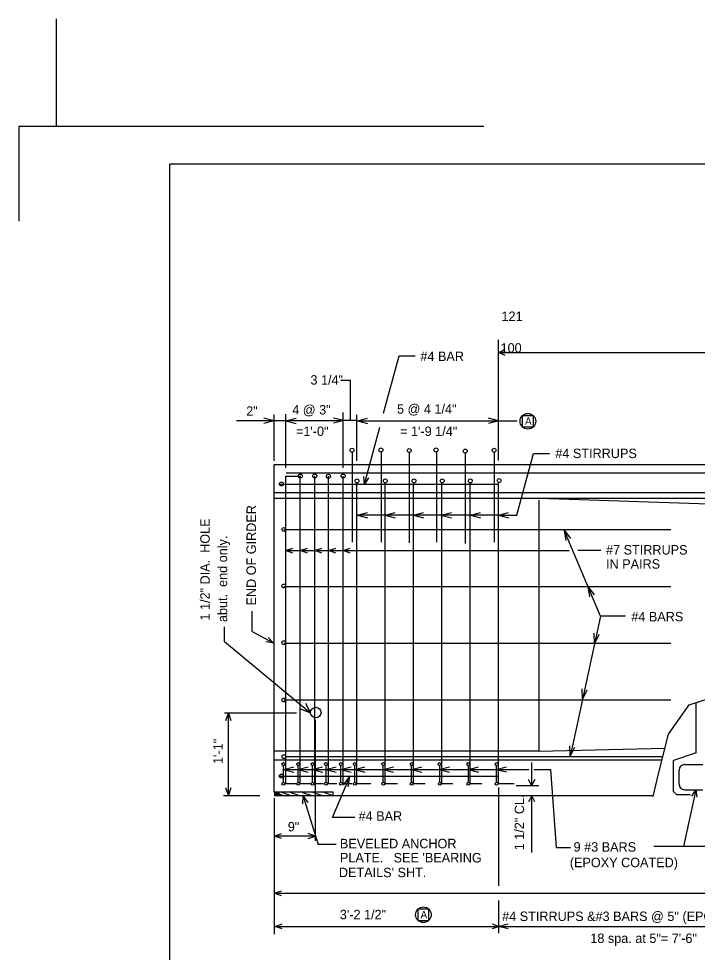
# Model space of a CAD drawing. Extents: x 1005 to 1133, y 2006 to 2074.
# Drawn here: x 1008.43 to 1032.36, y 2040.77 to 2073.7 of the extents above; entities that cross this region are included whole.
import ezdxf

# ---------------------------------------------------------------- set-up
doc = ezdxf.new("R2010")
doc.units = 0
for name, color, linetype in [('Level 1', 7, 'Continuous'), ('Level 2', 7, 'Continuous'), ('Level 5', 7, 'Continuous'), ('Level 6', 7, 'Continuous'), ('Level 60', 7, 'Continuous')]:
    doc.layers.add(name, color=color, linetype=linetype)

msp = doc.modelspace()

# ---------------------------------------------------------------- linework, layer by layer
at = {"layer": 'Level 1'}
for p, q in [((1024.831, 2069.894), (1008.43, 2069.894)), ((1008.43, 2069.894), (1008.43, 2066.554)), ((1013.763, 2012.562), (1013.763, 2068.561)), ((1097.431, 2068.561), (1013.763, 2068.561))]:
    msp.add_line(p, q, dxfattribs=at)
at = {"layer": 'Level 2'}
for p, q in [((1009.763, 2069.894), (1009.763, 2073.698)), ((1025.357, 2058.113), (1025.357, 2062.376)), ((1021.298, 2059.783), (1021.846, 2061.808)), ((1021.846, 2061.808), (1022.41, 2061.808)), ((1025.357, 2061.923), (1054.324, 2061.923)), ((1020.13, 2060.939), (1019.792, 2060.939)), ((1020.13, 2059.522), (1020.13, 2060.939)), ((1019.87, 2057.862), (1019.87, 2059.809)), ((1017.857, 2059.514), (1016.107, 2059.514)), ((1017.441, 2059.514), (1016.171, 2059.514)), ((1017.441, 2059.514), (1017.081, 2059.604)), ((1017.441, 2059.514), (1017.081, 2059.424)), ((1017.441, 2058.106), (1017.441, 2059.732)), ((1017.857, 2057.854), (1017.857, 2059.744)), ((1017.857, 2059.514), (1018.217, 2059.604)), ((1019.87, 2059.514), (1017.857, 2059.514)), ((1017.857, 2059.514), (1018.217, 2059.424)), ((1019.898, 2059.522), (1019.538, 2059.612)), ((1019.898, 2059.522), (1019.538, 2059.432)), ((1020.36, 2059.522), (1019.87, 2059.522)), ((1020.36, 2058.103), (1020.36, 2059.725)), ((1020.36, 2059.514), (1026.005, 2059.514)), ((1020.375, 2059.514), (1020.735, 2059.604)), ((1020.375, 2059.514), (1020.735, 2059.424)), ((1025.357, 2059.514), (1024.997, 2059.604)), ((1025.357, 2059.514), (1024.997, 2059.424)), ((1020.621, 2057.286), (1021.163, 2059.286)), ((1026.195, 2059.303), (1026.195, 2059.303)), ((1020.194, 2058.425), (1020.194, 2055.229)), ((1021.21, 2058.425), (1021.21, 2055.229)), ((1022.207, 2058.404), (1022.207, 2055.208)), ((1023.161, 2058.425), (1023.161, 2055.229)), ((1024.178, 2058.383), (1024.178, 2055.187)), ((1025.195, 2058.425), (1025.195, 2055.229)), ((1025.994, 2056.185), (1026.584, 2058.362)), ((1026.584, 2058.362), (1027.147, 2058.362)), ((1017.441, 2046.413), (1017.441, 2057.969)), ((1017.441, 2057.969), (1038.737, 2057.969)), ((1017.857, 2057.562), (1018.382, 2057.562)), ((1017.857, 2047.379), (1017.857, 2057.562)), ((1017.863, 2057.676), (1031.429, 2057.676)), ((1018.362, 2046.728), (1018.362, 2057.562)), ((1018.87, 2046.728), (1018.87, 2057.562)), ((1019.357, 2046.728), (1019.357, 2057.562)), ((1019.87, 2046.728), (1019.87, 2057.562)), ((1031.429, 2057.676), (1038.745, 2057.676)), ((1017.64, 2057.286), (1025.357, 2057.286)), ((1020.357, 2046.728), (1020.357, 2057.335)), ((1021.357, 2046.728), (1021.357, 2057.335)), ((1022.357, 2046.728), (1022.357, 2057.325)), ((1023.357, 2046.728), (1023.357, 2057.335)), ((1024.357, 2046.728), (1024.357, 2057.325)), ((1025.357, 2046.728), (1025.357, 2057.335)), ((1038.745, 2056.969), (1017.439, 2056.969)), ((1038.737, 2056.772), (1017.426, 2056.772)), ((1038.441, 2056.386), (1026.782, 2056.772)), ((1026.782, 2047.859), (1026.782, 2056.719)), ((1020.374, 2056.185), (1020.734, 2056.275)), ((1022.351, 2056.185), (1020.374, 2056.185)), ((1020.374, 2056.185), (1020.734, 2056.095)), ((1021.349, 2056.185), (1021.709, 2056.275)), ((1021.349, 2056.185), (1021.709, 2056.095)), ((1022.351, 2056.185), (1022.711, 2056.275)), ((1023.284, 2056.185), (1022.351, 2056.185)), ((1022.351, 2056.185), (1022.711, 2056.095)), ((1023.333, 2056.185), (1023.284, 2056.185)), ((1023.333, 2056.185), (1023.693, 2056.275)), ((1024.362, 2056.185), (1023.333, 2056.185)), ((1023.333, 2056.185), (1023.693, 2056.095)), ((1024.362, 2056.185), (1024.722, 2056.275)), ((1025.347, 2056.185), (1024.362, 2056.185)), ((1024.362, 2056.185), (1024.722, 2056.095)), ((1025.347, 2056.185), (1025.707, 2056.275)), ((1025.347, 2056.185), (1025.994, 2056.185)), ((1025.347, 2056.185), (1025.707, 2056.095)), ((1017.78, 2055.676), (1031.429, 2055.676)), ((1028.945, 2052.627), (1027.669, 2055.663)), ((1027.669, 2055.663), (1027.892, 2055.366)), ((1027.669, 2055.663), (1027.726, 2055.296)), ((1017.842, 2054.936), (1027.842, 2054.936)), ((1028.958, 2054.936), (1028.149, 2054.936)), ((1017.78, 2053.676), (1031.429, 2053.676)), ((1028.504, 2053.676), (1028.726, 2053.379)), ((1028.504, 2053.676), (1028.561, 2053.31)), ((1016.66, 2052.086), (1016.66, 2052.795)), ((1028.945, 2052.627), (1028.735, 2051.653)), ((1029.834, 2052.627), (1028.945, 2052.627)), ((1016.66, 2052.086), (1017.41, 2051.679)), ((1028.735, 2051.653), (1028.723, 2052.024)), ((1028.735, 2051.653), (1028.899, 2051.986)), ((1017.78, 2051.676), (1031.429, 2051.676)), ((1028.735, 2051.653), (1028.311, 2049.688)), ((1028.311, 2049.688), (1028.299, 2050.059)), ((1028.311, 2049.688), (1028.475, 2050.021)), ((1017.78, 2049.676), (1023.804, 2049.676)), ((1023.804, 2049.676), (1031.429, 2049.676)), ((1028.311, 2049.688), (1027.876, 2047.676)), ((1032.321, 2047.81), (1032.321, 2049.575)), ((1026.782, 2047.859), (1031.222, 2047.964)), ((1027.876, 2047.676), (1027.864, 2048.047)), ((1027.876, 2047.676), (1028.04, 2048.009)), ((1026.782, 2047.859), (1017.441, 2047.859)), ((1017.85, 2047.676), (1031.149, 2047.676)), ((1032.321, 2047.81), (1031.518, 2047.528)), ((1017.44, 2047.552), (1031.118, 2047.552)), ((1017.769, 2046.782), (1017.769, 2047.355)), ((1017.769, 2047.216), (1018.129, 2047.306)), ((1017.857, 2046.728), (1017.857, 2047.379)), ((1018.28, 2047.216), (1018.64, 2047.306)), ((1018.284, 2046.782), (1018.284, 2047.355)), ((1018.789, 2047.216), (1019.149, 2047.306)), ((1018.793, 2046.782), (1018.793, 2047.355)), ((1019.265, 2047.216), (1019.625, 2047.306)), ((1019.271, 2046.782), (1019.271, 2047.355)), ((1019.79, 2047.215), (1020.15, 2047.305)), ((1019.793, 2046.782), (1019.793, 2047.355)), ((1020.283, 2047.216), (1020.643, 2047.306)), ((1020.286, 2046.782), (1020.286, 2047.355)), ((1021.289, 2046.782), (1021.289, 2047.355)), ((1021.29, 2047.216), (1021.65, 2047.306)), ((1022.289, 2046.782), (1022.289, 2047.379)), ((1022.289, 2047.216), (1022.649, 2047.306)), ((1023.258, 2047.216), (1023.618, 2047.306)), ((1023.278, 2046.782), (1023.278, 2047.379)), ((1024.289, 2046.782), (1024.289, 2047.379)), ((1024.289, 2047.216), (1024.649, 2047.306)), ((1025.274, 2047.22), (1025.634, 2047.31)), ((1025.284, 2046.782), (1025.284, 2047.379)), ((1026.512, 2047.469), (1026.512, 2046.649)), ((1031.518, 2046.444), (1031.518, 2047.528)), ((1031.912, 2047.388), (1032.556, 2047.388)), ((1017.64, 2046.986), (1025.357, 2046.986)), ((1017.769, 2047.216), (1018.53, 2047.216)), ((1017.769, 2047.216), (1018.129, 2047.126)), ((1018.28, 2047.216), (1018.64, 2047.126)), ((1018.53, 2047.216), (1019.251, 2047.216)), ((1018.789, 2047.216), (1019.149, 2047.126)), ((1019.251, 2047.216), (1020.274, 2047.216)), ((1019.265, 2047.216), (1019.625, 2047.126)), ((1019.499, 2045.521), (1020.103, 2046.973)), ((1019.79, 2047.215), (1020.15, 2047.125)), ((1020.099, 2046.971), (1019.877, 2046.673)), ((1020.099, 2046.971), (1020.043, 2046.604)), ((1020.274, 2047.216), (1021.29, 2047.216)), ((1020.283, 2047.216), (1020.643, 2047.126)), ((1021.29, 2047.216), (1023.258, 2047.216)), ((1021.29, 2047.216), (1021.65, 2047.126)), ((1022.289, 2047.216), (1022.649, 2047.126)), ((1023.258, 2047.216), (1025.358, 2047.216)), ((1023.258, 2047.216), (1023.618, 2047.126)), ((1024.289, 2047.216), (1024.649, 2047.126)), ((1025.274, 2047.22), (1025.634, 2047.13)), ((1025.358, 2047.216), (1026.419, 2047.216)), ((1026.595, 2047.216), (1027.202, 2047.216)), ((1027.399, 2044.471), (1027.202, 2047.216)), ((1031.719, 2046.697), (1031.719, 2047.195)), ((1017.857, 2046.728), (1017.857, 2046.765)), ((1017.857, 2046.728), (1018.202, 2046.728)), ((1018.362, 2046.728), (1018.706, 2046.728)), ((1018.87, 2046.728), (1019.174, 2046.728)), ((1019.357, 2046.728), (1019.648, 2046.728)), ((1019.87, 2046.728), (1020.186, 2046.728)), ((1020.357, 2046.728), (1020.851, 2046.728)), ((1021.357, 2046.728), (1021.793, 2046.728)), ((1022.359, 2046.728), (1022.762, 2046.728)), ((1023.357, 2046.728), (1023.743, 2046.728)), ((1024.364, 2046.728), (1024.762, 2046.728)), ((1025.357, 2046.728), (1025.906, 2046.728)), ((1025.97, 2046.649), (1026.774, 2046.649)), ((1017.441, 2046.413), (1017.769, 2046.301)), ((1017.769, 2046.302), (1030.816, 2046.302)), ((1025.357, 2046.576), (1025.357, 2043.109)), ((1026.512, 2046.302), (1026.512, 2044.294)), ((1026.834, 2046.302), (1026.901, 2046.302)), ((1031.639, 2046.323), (1031.518, 2046.444)), ((1032.126, 2046.323), (1031.639, 2046.323)), ((1032.311, 2046.503), (1031.873, 2044.502)), ((1031.912, 2046.504), (1032.556, 2046.504)), ((1017.441, 2046.208), (1017.441, 2041.404)), ((1020.283, 2045.521), (1019.499, 2045.521)), ((1027.399, 2044.471), (1027.892, 2044.471)), ((1034.63, 2044.502), (1030.834, 2044.502)), ((1017.441, 2042.85), (1061.731, 2042.85)), ((1025.357, 2042.592), (1025.357, 2041.445)), ((1017.463, 2041.684), (1025.357, 2041.684)), ((1022.511, 2041.897), (1022.511, 2041.897)), ((1025.357, 2041.684), (1037.408, 2041.684))]:
    msp.add_line(p, q, dxfattribs=at)
for points in [[(1025.59, 2061.815), (1025.368, 2061.926), (1025.59, 2062.037)], [(1020.772, 2057.507), (1020.621, 2057.286), (1020.603, 2057.553)], [(1018.095, 2054.848), (1017.842, 2054.936), (1018.095, 2055.024)], [(1018.614, 2054.848), (1018.361, 2054.936), (1018.614, 2055.024)], [(1019.123, 2054.848), (1018.87, 2054.936), (1019.123, 2055.024)], [(1019.611, 2054.848), (1019.357, 2054.936), (1019.611, 2055.024)], [(1020.123, 2054.848), (1019.87, 2054.936), (1020.123, 2055.024)], [(1017.229, 2051.877), (1017.41, 2051.679), (1017.145, 2051.723)], [(1030.807, 2046.261), (1030.995, 2047.069), (1031.348, 2048.459), (1032.076, 2049.496), (1033.422, 2049.93), (1034.422, 2049.9), (1035.084, 2049.599), (1035.406, 2049.287)], [(1026.628, 2046.869), (1026.517, 2046.647), (1026.406, 2046.869)], [(1032.171, 2046.274), (1032.311, 2046.503), (1032.343, 2046.237)], [(1026.634, 2046.071), (1026.523, 2046.293), (1026.411, 2046.071)], [(1017.694, 2042.763), (1017.441, 2042.85), (1017.694, 2042.938)], [(1017.724, 2041.597), (1017.471, 2041.684), (1017.724, 2041.772)], [(1025.124, 2041.772), (1025.378, 2041.684), (1025.124, 2041.597)], [(1025.691, 2041.601), (1025.357, 2041.684), (1025.691, 2041.768)]]:
    msp.add_lwpolyline(points, dxfattribs=at)
for points in [[(1026.191, 2059.694), (1026.191, 2059.302), (1026.583, 2059.302), (1026.583, 2059.694)], [(1022.506, 2042.288), (1022.506, 2041.895), (1022.898, 2041.895), (1022.898, 2042.288)]]:
    msp.add_lwpolyline(points, close=True, dxfattribs=at)
for centre, radius in [((1026.388, 2059.499), 0.277), ((1020.184, 2058.477), 0.0694), ((1021.203, 2058.487), 0.0694), ((1022.202, 2058.467), 0.0694), ((1023.149, 2058.487), 0.0694), ((1024.178, 2058.446), 0.0694), ((1025.198, 2058.477), 0.0694), ((1018.362, 2057.568), 0.0694), ((1018.871, 2057.568), 0.0694), ((1019.352, 2057.558), 0.0694), ((1019.871, 2057.568), 0.0694), ((1017.697, 2057.288), 0.0694), ((1020.36, 2057.397), 0.0694), ((1021.358, 2057.397), 0.0694), ((1022.372, 2057.397), 0.0694), ((1023.366, 2057.397), 0.0694), ((1024.359, 2057.397), 0.0694), ((1025.375, 2057.408), 0.0694), ((1017.781, 2055.681), 0.0694), ((1017.781, 2053.689), 0.0694), ((1017.781, 2051.688), 0.0694), ((1017.781, 2049.669), 0.0694), ((1017.781, 2047.668), 0.0694), ((1017.767, 2047.407), 0.052), ((1018.287, 2047.407), 0.052), ((1018.796, 2047.407), 0.052), ((1019.269, 2047.407), 0.052), ((1019.796, 2047.407), 0.052), ((1020.287, 2047.407), 0.052), ((1021.291, 2047.407), 0.052), ((1022.291, 2047.407), 0.052), ((1023.274, 2047.407), 0.052), ((1024.291, 2047.407), 0.052), ((1025.286, 2047.407), 0.052), ((1017.697, 2046.984), 0.0694), ((1017.767, 2046.713), 0.052), ((1018.287, 2046.713), 0.052), ((1018.796, 2046.713), 0.052), ((1019.269, 2046.713), 0.052), ((1019.796, 2046.713), 0.052), ((1020.287, 2046.713), 0.052), ((1021.291, 2046.713), 0.052), ((1022.291, 2046.713), 0.052), ((1023.282, 2046.713), 0.052), ((1024.291, 2046.713), 0.052), ((1025.286, 2046.713), 0.052), ((1022.703, 2042.093), 0.277)]:
    msp.add_circle(centre, radius, dxfattribs=at)
for centre, start, end in [((1031.912, 2047.195), 90, 180), ((1031.912, 2046.697), 180, 270)]:
    msp.add_arc(centre, 0.193, start, end, dxfattribs=at)
at = {"layer": 'Level 5'}
for p, q in [((1015.685, 2051.734), (1015.685, 2052.253)), ((1015.685, 2051.734), (1018.731, 2049.207)), ((1018.731, 2049.207), (1018.349, 2049.352)), ((1018.731, 2049.207), (1018.562, 2049.539)), ((1018.232, 2049.203), (1015.688, 2049.203)), ((1015.829, 2046.311), (1015.829, 2049.201)), ((1018.888, 2048.97), (1018.888, 2044.7)), ((1016.94, 2046.287), (1015.65, 2046.287)), ((1018.888, 2044.867), (1017.441, 2044.867))]:
    msp.add_line(p, q, dxfattribs=at)
for points in [[(1015.741, 2048.948), (1015.829, 2049.201), (1015.916, 2048.948)], [(1015.741, 2048.948), (1015.829, 2049.201), (1015.916, 2048.948)], [(1015.916, 2046.565), (1015.829, 2046.311), (1015.741, 2046.565)], [(1017.694, 2044.779), (1017.441, 2044.867), (1017.694, 2044.955)], [(1018.641, 2044.779), (1018.894, 2044.867), (1018.641, 2044.955)]]:
    msp.add_lwpolyline(points, dxfattribs=at)
msp.add_circle((1018.906, 2049.225), 0.186, dxfattribs=at)
at = {"layer": 'Level 6'}
for p, q in [((1017.609, 2046.413), (1017.441, 2046.413)), ((1017.441, 2046.405), (1017.609, 2046.405)), ((1017.441, 2046.395), (1017.609, 2046.395)), ((1017.441, 2046.385), (1017.609, 2046.385)), ((1017.441, 2046.375), (1017.609, 2046.375)), ((1017.441, 2046.365), (1017.609, 2046.365)), ((1017.441, 2046.355), (1017.609, 2046.355)), ((1017.441, 2046.345), (1017.609, 2046.345)), ((1017.441, 2046.335), (1017.609, 2046.335)), ((1017.441, 2046.325), (1017.609, 2046.325)), ((1017.441, 2046.315), (1017.609, 2046.315)), ((1017.441, 2046.305), (1017.609, 2046.305)), ((1017.609, 2046.302), (1017.441, 2046.302)), ((1017.698, 2046.413), (1018.025, 2046.302)), ((1017.999, 2046.413), (1018.327, 2046.301)), ((1018.44, 2046.41), (1018.768, 2046.299)), ((1018.803, 2046.413), (1019.131, 2046.302)), ((1019.188, 2046.415), (1019.515, 2046.304)), ((1018.466, 2046.274), (1018.99, 2044.573)), ((1019.632, 2044.573), (1018.99, 2044.573))]:
    msp.add_line(p, q, dxfattribs=at)
msp.add_lwpolyline([(1019.518, 2046.413), (1017.609, 2046.413), (1017.609, 2046.302), (1019.518, 2046.302)], close=True, dxfattribs=at)
msp.add_lwpolyline([(1018.457, 2046.006), (1018.466, 2046.274), (1018.625, 2046.058)], dxfattribs=at)

# ---------------------------------------------------------------- texts
at = {"layer": 'Level 2'}
for s, height, p in [('#4 BAR', 0.3333, (1022.597, 2061.623)), ('3 1/4"', 0.3333, (1018.72, 2060.79)), ('2"', 0.3333, (1016.454, 2059.691)), ('4 @ 3"', 0.3333, (1018.079, 2059.738)), ('5 @ 4 1/4"', 0.3333, (1021.773, 2059.767)), ('A', 0.261, (1026.288, 2059.374)), ('=1\'-0"', 0.3333, (1018.209, 2058.979)), ('= 1\'-9 1/4"', 0.33333, (1021.882, 2058.979)), ('#4 STIRRUPS', 0.33333, (1027.357, 2058.2)), ('#7 STIRRUPS', 0.33333, (1029.145, 2054.799)), ('IN PAIRS', 0.3333, (1029.145, 2054.299)), ('#4 BARS', 0.3333, (1030.036, 2052.441)), ('#4 BAR', 0.3333, (1020.418, 2045.406)), ('9 #3 BARS', 0.3333, (1028, 2044.319)), ('(EPOXY COATED)', 0.33333, (1027.867, 2043.77)), ('3\'-2 1/2"', 0.3333, (1019.756, 2041.933)), ('A', 0.261, (1022.603, 2041.967)), ('#4 STIRRUPS &#3 BARS @ 5" (EPOXY COATED)', 0.33333, (1025.48, 2041.872)), ('18 spa. at 5"= 7\'-6"', 0.33333, (1028.59, 2041.097))]:
    msp.add_text(s, height=height, dxfattribs=at).set_placement(p)
for s, height, p in [('END OF GIRDER', 0.33333, (1016.797, 2053.001)), ('1 1/2" CL.', 0.3333, (1026.254, 2044.367))]:
    msp.add_text(s, height=height, rotation=90, dxfattribs=at).set_placement(p)
at = {"layer": 'Level 5'}
for s, height, p in [('1 1/2" DIA.  HOLE', 0.33333, (1015.167, 2052.47)), ('abut.  end only.', 0.33333, (1015.783, 2052.417)), ('1\'-1"', 0.3333, (1015.626, 2047.411))]:
    msp.add_text(s, height=height, rotation=90, dxfattribs=at).set_placement(p)
msp.add_text('9"', height=0.3333, dxfattribs=at).set_placement((1017.92, 2045.033))
at = {"layer": 'Level 6'}
for s, height, p in [('BEVELED ANCHOR', 0.33333, (1019.759, 2044.438)), ('PLATE.', 0.3333, (1019.759, 2043.938)), ("SEE 'BEARING", 0.33333, (1021.654, 2043.938)), ("DETAILS' SHT.", 0.33333, (1019.724, 2043.419))]:
    msp.add_text(s, height=height, dxfattribs=at).set_placement(p)
at = {"layer": 'Level 60'}
for s, p in [('121', (1025.457, 2063.035)), ('100', (1025.425, 2061.918))]:
    msp.add_text(s, height=0.3333, dxfattribs=at).set_placement(p)

doc.saveas('drawing.dxf')
